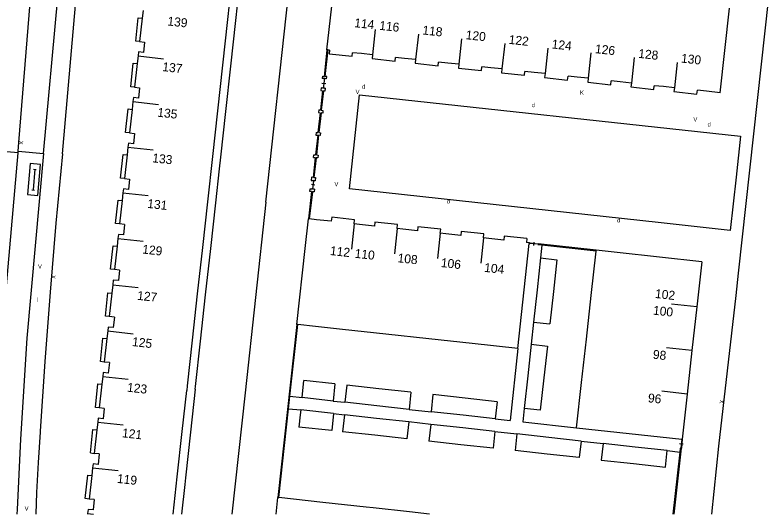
# Model space of a CAD drawing. Extents: x 134999 to 136502, y 457398 to 459002.
# Drawn here: x 136333.3 to 136421.3, y 457400 to 457458.7 of the extents above; entities that cross this region are included whole.
import ezdxf

# ---------------------------------------------------------------- set-up
doc = ezdxf.new("R2010")
doc.units = 0
for name, color, linetype in [('RI_DGTB_15', 7, 'Continuous'), ('RI_DGTB_2', 7, 'Continuous'), ('RI_DGTB_23', 7, 'Continuous'), ('RI_DGTB_29', 7, 'Continuous'), ('RI_DGTB_30', 7, 'Continuous'), ('RI_DGTB_35', 7, 'Continuous'), ('RI_DGTB_36', 7, 'Continuous'), ('RI_DGTB_43', 7, 'Continuous'), ('RI_DGTB_53', 7, 'Continuous'), ('RI_DGTB_6', 7, 'Continuous'), ('RI_DGTB_7', 7, 'Continuous')]:
    doc.layers.add(name, color=color, linetype=linetype)

msp = doc.modelspace()

# ---------------------------------------------------------------- linework, layer by layer
at = {"layer": 'RI_DGTB_15'}
for p, q in [((136375.693, 457457.011), (136375.37, 457454.029)), ((136380.759, 457456.46), (136380.436, 457453.478)), ((136385.836, 457455.908), (136385.513, 457452.926)), ((136390.911, 457455.355), (136390.588, 457452.373)), ((136395.98, 457454.804), (136395.657, 457451.822)), ((136347.786, 457453.897), (136350.769, 457453.574)), ((136401.048, 457454.252), (136400.725, 457451.27)), ((136406.126, 457453.699), (136405.803, 457450.717)), ((136411.188, 457453.149), (136410.865, 457450.167)), ((136347.196, 457448.531), (136350.179, 457448.208)), ((136346.604, 457443.163), (136349.587, 457442.84)), ((136346.013, 457437.796), (136348.996, 457437.473)), ((136373.2, 457434.152), (136372.877, 457431.17)), ((136378.274, 457433.598), (136377.951, 457430.616)), ((136345.422, 457432.428), (136348.405, 457432.105)), ((136383.334, 457433.046), (136383.011, 457430.064)), ((136388.421, 457432.489), (136388.098, 457429.507)), ((136344.823, 457426.986), (136347.806, 457426.663)), ((136413.492, 457424.368), (136410.51, 457424.692)), ((136344.224, 457421.544), (136347.207, 457421.221)), ((136412.918, 457419.244), (136409.936, 457419.568)), ((136343.634, 457416.176), (136346.617, 457415.853)), ((136412.368, 457414.117), (136409.386, 457414.441)), ((136343.043, 457410.808), (136346.026, 457410.485)), ((136342.451, 457405.441), (136345.434, 457405.118)), ((136341.86, 457400.073), (136342.538, 457400))]:
    msp.add_line(p, q, dxfattribs=at)
at = {"layer": 'RI_DGTB_2'}
for p, q in [((136369.997, 457454.628), (136371.381, 457467.081)), ((136416.252, 457449.58), (136417.345, 457459.531)), ((136347.52, 457455.642), (136347.823, 457458.405)), ((136347.823, 457458.405), (136348.277, 457458.355)), ((136347.973, 457455.592), (136347.52, 457455.642)), ((136374.068, 457454.171), (136372.999, 457454.287)), ((136375.37, 457454.029), (136374.068, 457454.171)), ((136379.141, 457453.619), (136378.072, 457453.736)), ((136380.436, 457453.478), (136379.141, 457453.619)), ((136346.928, 457450.28), (136347.233, 457453.043)), ((136347.233, 457453.043), (136347.687, 457452.993)), ((136384.207, 457453.068), (136383.138, 457453.185)), ((136385.513, 457452.926), (136384.207, 457453.068)), ((136389.284, 457452.515), (136388.215, 457452.632)), ((136390.588, 457452.373), (136389.284, 457452.515)), ((136394.358, 457451.963), (136393.289, 457452.079)), ((136395.657, 457451.822), (136394.358, 457451.963)), ((136399.427, 457451.411), (136398.358, 457451.527)), ((136400.725, 457451.27), (136399.427, 457451.411)), ((136404.495, 457450.86), (136403.426, 457450.976)), ((136405.803, 457450.717), (136404.495, 457450.86)), ((136409.573, 457450.307), (136408.502, 457450.397)), ((136410.865, 457450.167), (136409.573, 457450.307)), ((136414.636, 457449.756), (136413.567, 457449.872)), ((136416.252, 457449.58), (136414.636, 457449.756)), ((136346.309, 457444.9), (136346.64, 457447.66)), ((136346.79, 457444.847), (136346.309, 457444.9)), ((136345.746, 457439.537), (136346.05, 457442.3)), ((136346.05, 457442.3), (136346.504, 457442.25)), ((136346.2, 457439.487), (136345.746, 457439.537)), ((136345.155, 457434.18), (136345.459, 457436.942)), ((136345.459, 457436.942), (136345.914, 457436.892)), ((136345.61, 457434.129), (136345.155, 457434.18)), ((136346.206, 457434.063), (136345.61, 457434.129)), ((136367.451, 457431.244), (136367.827, 457434.739)), ((136373.254, 457434.621), (136370.57, 457434.914)), ((136378.318, 457434.068), (136375.634, 457434.361)), ((136383.39, 457433.514), (136380.705, 457433.807)), ((136383.334, 457433.046), (136383.39, 457433.514)), ((136388.46, 457432.96), (136385.776, 457433.254)), ((136346.071, 457432.84), (136345.475, 457432.907)), ((136388.421, 457432.489), (136388.46, 457432.96)), ((136393.53, 457432.407), (136390.845, 457432.7)), ((136393.53, 457432.407), (136393.479, 457431.939)), ((136344.564, 457428.811), (136344.869, 457431.574)), ((136344.869, 457431.574), (136345.323, 457431.524)), ((136393.81, 457431.903), (136393.479, 457431.939)), ((136366.477, 457422.312), (136367.451, 457431.244)), ((136404.135, 457430.777), (136401.661, 457431.047)), ((136414.089, 457429.69), (136404.135, 457430.777)), ((136345.019, 457428.761), (136344.564, 457428.811)), ((136345.615, 457428.695), (136345.019, 457428.761)), ((136345.48, 457427.473), (136344.884, 457427.538)), ((136343.95, 457423.279), (136344.253, 457426.042)), ((136344.253, 457426.042), (136344.714, 457425.991)), ((136345.006, 457423.162), (136344.41, 457423.228)), ((136343.363, 457417.931), (136343.666, 457420.694)), ((136343.666, 457420.694), (136344.125, 457420.644)), ((136343.821, 457417.881), (136343.363, 457417.931)), ((136344.417, 457417.815), (136343.821, 457417.881)), ((136344.283, 457416.593), (136343.687, 457416.658)), ((136342.775, 457412.551), (136343.078, 457415.314)), ((136343.078, 457415.314), (136343.533, 457415.264)), ((136343.229, 457412.501), (136342.775, 457412.551)), ((136343.825, 457412.435), (136343.229, 457412.501)), ((136343.69, 457411.212), (136343.095, 457411.278)), ((136342.184, 457407.184), (136342.488, 457409.947)), ((136342.488, 457409.947), (136342.942, 457409.897)), ((136342.184, 457407.184), (136342.638, 457407.134)), ((136343.234, 457407.068), (136342.638, 457407.134)), ((136343.099, 457405.845), (136342.503, 457405.911)), ((136341.592, 457401.815), (136341.897, 457404.578)), ((136341.897, 457404.578), (136342.351, 457404.528)), ((136353.289, 457403.463), (136352.889, 457400)), ((136342.643, 457401.699), (136342.047, 457401.765)), ((136364.023, 457400), (136364.238, 457401.954))]:
    msp.add_line(p, q, dxfattribs=at)
for points in [[(136358.892, 457463.632), (136358.296, 457458.189)], [(136359.278, 457458.082), (136359.875, 457463.525)], [(136348.377, 457459.266), (136348.277, 457458.355)], [(136348.277, 457458.355), (136347.973, 457455.592)], [(136358.296, 457458.189), (136357.708, 457452.821)], [(136358.69, 457452.714), (136359.278, 457458.082)], [(136347.973, 457455.592), (136348.569, 457455.526)], [(136348.569, 457455.526), (136348.434, 457454.303)], [(136347.838, 457454.369), (136347.786, 457453.897)], [(136348.434, 457454.303), (136347.838, 457454.369)], [(136370.093, 457454.617), (136369.997, 457454.628)], [(136370.299, 457454.592), (136370.093, 457454.617)], [(136370.299, 457454.592), (136370.253, 457454.157), (136372.953, 457453.863)], [(136347.786, 457453.897), (136347.687, 457452.993)], [(136372.953, 457453.863), (136372.999, 457454.287)], [(136375.37, 457454.029), (136375.325, 457453.6), (136378.025, 457453.306)], [(136378.025, 457453.306), (136378.072, 457453.736)], [(136347.687, 457452.993), (136347.383, 457450.23)], [(136357.708, 457452.821), (136357.12, 457447.454)], [(136358.102, 457447.347), (136358.69, 457452.714)], [(136380.436, 457453.478), (136380.39, 457453.04), (136383.09, 457452.746)], [(136383.09, 457452.746), (136383.138, 457453.185)], [(136385.513, 457452.926), (136385.466, 457452.481), (136388.166, 457452.187)], [(136388.166, 457452.187), (136388.215, 457452.632)], [(136390.588, 457452.373), (136390.541, 457451.931), (136393.241, 457451.637)], [(136393.241, 457451.637), (136393.289, 457452.079)], [(136395.657, 457451.822), (136395.608, 457451.36), (136398.308, 457451.066)], [(136398.308, 457451.066), (136398.358, 457451.527)], [(136400.725, 457451.27), (136400.676, 457450.808), (136403.376, 457450.514)], [(136403.376, 457450.514), (136403.426, 457450.976)], [(136347.383, 457450.23), (136346.928, 457450.28)], [(136347.383, 457450.23), (136347.979, 457450.164)], [(136347.979, 457450.164), (136347.844, 457448.942)], [(136405.803, 457450.717), (136405.755, 457450.261), (136408.455, 457449.967)], [(136408.455, 457449.967), (136408.502, 457450.397)], [(136410.865, 457450.167), (136410.817, 457449.708), (136413.517, 457449.414)], [(136413.517, 457449.414), (136413.567, 457449.872)], [(136347.196, 457448.531), (136347.094, 457447.61)], [(136347.248, 457449.007), (136347.196, 457448.531)], [(136347.844, 457448.942), (136347.248, 457449.007)], [(136346.64, 457447.66), (136347.094, 457447.61)], [(136347.094, 457447.61), (136346.79, 457444.847)], [(136357.12, 457447.454), (136356.532, 457442.085)], [(136357.514, 457441.978), (136358.102, 457447.347)], [(136346.79, 457444.847), (136347.386, 457444.781)], [(136347.386, 457444.781), (136347.251, 457443.558)], [(136346.604, 457443.163), (136346.504, 457442.25)], [(136346.655, 457443.624), (136346.604, 457443.163)], [(136347.251, 457443.558), (136346.655, 457443.624)], [(136346.504, 457442.25), (136346.2, 457439.487)], [(136356.532, 457442.085), (136355.944, 457436.717)], [(136357.367, 457440.638), (136357.514, 457441.978)], [(136356.924, 457436.611), (136357.367, 457440.638)], [(136346.2, 457439.487), (136346.796, 457439.421)], [(136346.796, 457439.421), (136346.661, 457438.198)], [(136346.013, 457437.796), (136345.914, 457436.892)], [(136346.065, 457438.264), (136346.013, 457437.796)], [(136346.661, 457438.198), (136346.065, 457438.264)], [(136345.914, 457436.892), (136345.61, 457434.129)], [(136355.944, 457436.717), (136355.356, 457431.349)], [(136356.334, 457431.243), (136356.924, 457436.611)], [(136367.831, 457434.739), (136367.827, 457434.739)], [(136367.93, 457434.728), (136367.831, 457434.739)], [(136368.776, 457434.635), (136367.93, 457434.728)], [(136370.516, 457434.445), (136368.776, 457434.635)], [(136370.57, 457434.914), (136370.516, 457434.445)], [(136373.2, 457434.152), (136373.254, 457434.621)], [(136373.843, 457434.082), (136373.2, 457434.152)], [(136375.634, 457434.361), (136375.583, 457433.892)], [(136346.206, 457434.063), (136346.071, 457432.84)], [(136375.583, 457433.892), (136373.843, 457434.082)], [(136378.274, 457433.598), (136378.318, 457434.068)], [(136378.927, 457433.527), (136378.274, 457433.598)], [(136380.667, 457433.337), (136378.927, 457433.527)], [(136380.705, 457433.807), (136380.667, 457433.337)], [(136385.776, 457433.254), (136385.737, 457432.784)], [(136345.422, 457432.428), (136345.323, 457431.524)], [(136345.475, 457432.907), (136345.422, 457432.428)], [(136383.997, 457432.974), (136383.334, 457433.046)], [(136385.737, 457432.784), (136383.997, 457432.974)], [(136389.054, 457432.42), (136388.421, 457432.489)], [(136390.794, 457432.231), (136389.054, 457432.42)], [(136390.845, 457432.7), (136390.794, 457432.231)], [(136345.323, 457431.524), (136345.019, 457428.761)], [(136392.461, 457419.469), (136393.804, 457431.852)], [(136393.804, 457431.852), (136393.81, 457431.903)], [(136355.356, 457431.349), (136354.76, 457425.906)], [(136355.736, 457425.8), (136356.334, 457431.243)], [(136401.076, 457425.716), (136401.65, 457430.948)], [(136401.65, 457430.948), (136401.661, 457431.047)], [(136414.089, 457429.69), (136413.492, 457424.368)], [(136345.615, 457428.695), (136345.48, 457427.473)], [(136344.884, 457427.538), (136344.823, 457426.986)], [(136344.823, 457426.986), (136344.714, 457425.991)], [(136344.714, 457425.991), (136344.41, 457423.228)], [(136354.76, 457425.906), (136354.164, 457420.464)], [(136355.138, 457420.358), (136355.736, 457425.8)], [(136400.513, 457420.59), (136401.076, 457425.716)], [(136413.492, 457424.368), (136412.918, 457419.244)], [(136344.41, 457423.228), (136343.95, 457423.279)], [(136345.006, 457423.162), (136344.871, 457421.939)], [(136344.275, 457422.005), (136344.224, 457421.544)], [(136344.871, 457421.939), (136344.275, 457422.005)], [(136366.595, 457422.299), (136366.477, 457422.312)], [(136368.643, 457422.074), (136366.595, 457422.299)], [(136371.851, 457421.723), (136368.643, 457422.074)], [(136344.224, 457421.544), (136344.125, 457420.644)], [(136376.925, 457421.168), (136371.851, 457421.723)], [(136381.985, 457420.615), (136376.925, 457421.168)], [(136344.125, 457420.644), (136343.821, 457417.881)], [(136354.164, 457420.464), (136353.575, 457415.097)], [(136354.548, 457414.991), (136355.138, 457420.358)], [(136387.072, 457420.059), (136381.985, 457420.615)], [(136392.461, 457419.469), (136387.072, 457420.059)], [(136399.951, 457415.465), (136400.513, 457420.59)], [(136412.918, 457419.244), (136412.368, 457414.117)], [(136344.417, 457417.815), (136344.283, 457416.593)], [(136343.687, 457416.658), (136343.634, 457416.176)], [(136343.634, 457416.176), (136343.533, 457415.264)], [(136343.533, 457415.264), (136343.229, 457412.501)], [(136353.575, 457415.097), (136353.514, 457414.536)], [(136354.517, 457414.709), (136354.548, 457414.991)], [(136399.368, 457410.154), (136399.951, 457415.465)], [(136352.982, 457409.729), (136353.514, 457414.536)], [(136354.517, 457414.709), (136353.961, 457409.623)], [(136412.368, 457414.117), (136411.796, 457408.793)], [(136343.825, 457412.435), (136343.69, 457411.212)], [(136343.095, 457411.278), (136343.043, 457410.808)], [(136343.043, 457410.808), (136342.942, 457409.897)], [(136342.942, 457409.897), (136342.638, 457407.134)], [(136352.387, 457404.362), (136352.982, 457409.729)], [(136353.961, 457409.623), (136353.375, 457404.255)], [(136399.368, 457410.154), (136411.747, 457408.798)], [(136411.747, 457408.798), (136411.796, 457408.793)], [(136343.234, 457407.068), (136343.099, 457405.845)], [(136342.451, 457405.441), (136342.351, 457404.528)], [(136342.503, 457405.911), (136342.451, 457405.441)], [(136342.351, 457404.528), (136342.047, 457401.765)], [(136351.904, 457400), (136352.387, 457404.362)], [(136353.375, 457404.255), (136353.289, 457403.463)], [(136342.047, 457401.765), (136341.592, 457401.815)], [(136342.643, 457401.699), (136342.508, 457400.477)], [(136364.238, 457401.954), (136364.341, 457401.943)], [(136369.519, 457401.375), (136364.341, 457401.943)], [(136374.615, 457400.815), (136369.519, 457401.375)], [(136379.709, 457400.257), (136375.426, 457400.726), (136374.615, 457400.815)], [(136341.86, 457400.073), (136341.852, 457400)], [(136341.912, 457400.542), (136341.86, 457400.073)], [(136342.508, 457400.477), (136341.912, 457400.542)], [(136382.055, 457400), (136379.709, 457400.257)]]:
    msp.add_lwpolyline(points, dxfattribs=at)
at = {"layer": 'RI_DGTB_23'}
for p, q in [((136393.81, 457431.903), (136394.864, 457431.788)), ((136411.796, 457408.793), (136411.681, 457407.739))]:
    msp.add_line(p, q, dxfattribs=at)
at = {"layer": 'RI_DGTB_29'}
for points in [[(136334.793, 457437.586), (136335.988, 457437.478), (136336.316, 457441.127), (136335.121, 457441.234), (136334.793, 457437.586)], [(136335.664, 457440.572), (136335.445, 457438.14)], [(136335.515, 457440.585), (136335.813, 457440.558)], [(136335.296, 457438.153), (136335.595, 457438.126)]]:
    msp.add_lwpolyline(points, dxfattribs=at)
at = {"layer": 'RI_DGTB_53'}
for p, q in [((136418.405, 457428.328), (136424.169, 457481.084)), ((136336.683, 457442.434), (136338.801, 457465.882)), ((136338.913, 457442.388), (136340.885, 457465.016)), ((136333.787, 457443.702), (136335.089, 457460.148)), ((136369.474, 457451.516), (136369.448, 457451.262)), ((136369.474, 457451.516), (136369.673, 457451.496)), ((136369.702, 457451.234), (136369.579, 457450.123)), ((136369.591, 457451.246), (136369.813, 457451.222)), ((136369.979, 457451.465), (136369.772, 457451.486)), ((136369.952, 457451.206), (136369.979, 457451.465)), ((136369.323, 457450.153), (136369.287, 457449.825)), ((136369.418, 457450.703), (136369.863, 457450.654)), ((136369.468, 457450.135), (136369.69, 457450.111)), ((136369.811, 457450.099), (136369.775, 457449.771)), ((136369.486, 457449.803), (136369.236, 457447.543)), ((136369.287, 457449.825), (136369.486, 457449.803)), ((136369.585, 457449.792), (136369.335, 457447.532)), ((136369.775, 457449.771), (136369.585, 457449.792)), ((136372.639, 457438.259), (136373.848, 457449.34)), ((136373.848, 457449.34), (136418.637, 457444.451)), ((136369.053, 457447.563), (136369.015, 457447.232)), ((136369.053, 457447.563), (136369.236, 457447.543)), ((136369.335, 457447.532), (136369.541, 457447.496)), ((136369.541, 457447.496), (136369.506, 457447.176)), ((136369.214, 457447.209), (136368.951, 457444.889)), ((136369.015, 457447.232), (136369.214, 457447.209)), ((136369.313, 457447.198), (136369.05, 457444.878)), ((136369.506, 457447.176), (136369.313, 457447.198)), ((136368.749, 457444.912), (136368.716, 457444.597)), ((136368.749, 457444.912), (136368.951, 457444.889)), ((136369.05, 457444.878), (136369.251, 457444.849)), ((136369.251, 457444.849), (136369.216, 457444.536)), ((136368.915, 457444.576), (136368.669, 457442.258)), ((136368.716, 457444.597), (136368.915, 457444.576)), ((136369.014, 457444.565), (136368.768, 457442.247)), ((136369.216, 457444.536), (136369.014, 457444.565)), ((136418.637, 457444.451), (136418.113, 457439.652)), ((136368.436, 457441.961), (136368.47, 457442.279)), ((136368.47, 457442.279), (136368.669, 457442.258)), ((136368.768, 457442.247), (136368.962, 457442.22)), ((136368.962, 457442.22), (136368.928, 457441.901)), ((136368.625, 457441.941), (136368.377, 457439.618)), ((136368.436, 457441.961), (136368.625, 457441.941)), ((136368.724, 457441.93), (136368.476, 457439.608)), ((136368.928, 457441.901), (136368.724, 457441.93)), ((136368.177, 457439.639), (136368.137, 457439.258)), ((136368.377, 457439.618), (136368.177, 457439.639)), ((136368.476, 457439.608), (136368.675, 457439.583)), ((136368.675, 457439.583), (136368.634, 457439.205)), ((136418.113, 457439.652), (136417.427, 457433.367)), ((136368.137, 457439.258), (136368.336, 457439.237)), ((136368.597, 457438.707), (136368.205, 457438.759)), ((136368.465, 457439.223), (136368.336, 457439.237)), ((136368.336, 457438.243), (136368.465, 457439.224)), ((136368.336, 457438.238), (136368.465, 457439.223)), ((136368.563, 457439.211), (136368.367, 457439.237)), ((136368.634, 457439.205), (136368.465, 457439.223)), ((136367.995, 457437.96), (136368.031, 457438.273)), ((136368.194, 457437.937), (136367.995, 457437.96)), ((136368.031, 457438.273), (136368.23, 457438.25)), ((136368.435, 457438.23), (136368.238, 457438.256)), ((136368.53, 457438.215), (136368.494, 457437.902)), ((136408.967, 457434.291), (136372.639, 457438.259)), ((136417.427, 457433.367), (136408.967, 457434.291)), ((136393.815, 457431.957), (136393.793, 457431.747)), ((136394.858, 457431.738), (136393.804, 457431.852)), ((136394.354, 457432.006), (136394.308, 457431.584)), ((136394.869, 457431.843), (136394.847, 457431.633)), ((136401.661, 457431.047), (136394.864, 457431.788)), ((136366.477, 457422.312), (136364.238, 457401.954)), ((136394.311, 457422.58), (136394.029, 457419.979)), ((136392.461, 457419.469), (136391.544, 457411.015)), ((136370.72, 457413.298), (136372.105, 457413.158)), ((136379.659, 457412.32), (136382.251, 457412.045)), ((136393.209, 457412.424), (136393.038, 457410.85)), ((136370.78, 457411.817), (136372.072, 457411.673)), ((136382.205, 457410.549), (136379.625, 457410.835)), ((136389.805, 457411.206), (136391.544, 457411.015)), ((136393.038, 457410.85), (136399.368, 457410.154)), ((136389.759, 457409.71), (136392.339, 457409.423)), ((136411.747, 457408.798), (136411.632, 457407.744)), ((136411.642, 457408.81), (136411.852, 457408.786)), ((136399.892, 457408.585), (136402.483, 457408.298)), ((136410.835, 457400), (136411.681, 457407.739)), ((136411.479, 457408.294), (136411.9, 457408.248)), ((136411.527, 457407.755), (136411.737, 457407.732)), ((136415.276, 457400), (136416.1, 457407.99)), ((136333.57, 457400.538), (136333.549, 457400))]:
    msp.add_line(p, q, dxfattribs=at)
for points in [[(136369.997, 457454.628), (136369.673, 457451.496)], [(136370.093, 457454.617), (136369.772, 457451.486)], [(136369.702, 457451.234), (136369.448, 457451.262)], [(136369.702, 457451.234), (136369.579, 457450.125)], [(136369.952, 457451.206), (136369.702, 457451.234)], [(136369.579, 457450.125), (136369.323, 457450.153)], [(136369.811, 457450.099), (136369.579, 457450.125)], [(136333.698, 457442.681), (136333.787, 457443.702)], [(136333.682, 457442.502), (136330.547, 457442.792), (136328.449, 457419.934), (136328.168, 457408.395), (136328.311, 457408.352)], [(136328.417, 457408.855), (136331.69, 457420.12), (136331.919, 457422.378), (136333.682, 457442.502)], [(136336.683, 457442.434), (136334.709, 457420.68), (136333.973, 457408.795), (136333.57, 457400.538)], [(136333.682, 457442.502), (136333.698, 457442.681)], [(136333.698, 457442.681), (136336.683, 457442.434)], [(136338.913, 457442.388), (136338.138, 457434.243), (136337.442, 457426.09), (136336.825, 457417.931), (136336.289, 457409.766), (136336.28, 457409.624)], [(136368.194, 457437.937), (136367.831, 457434.739)], [(136368.494, 457437.902), (136368.294, 457437.925), (136367.93, 457434.728)], [(136368.336, 457438.238), (136368.23, 457438.25)], [(136368.53, 457438.215), (136368.336, 457438.238)], [(136394.858, 457431.738), (136393.804, 457431.852)], [(136394.858, 457431.738), (136394.853, 457431.689)], [(136395.294, 457431.641), (136394.853, 457431.689)], [(136394.864, 457431.788), (136394.858, 457431.738)], [(136395.294, 457431.641), (136395.131, 457430.136)], [(136401.65, 457430.948), (136395.294, 457431.641)], [(136416.1, 457407.99), (136418.12, 457425.72), (136418.405, 457428.328)], [(136365.66, 457413.852), (136366.595, 457422.299)], [(136365.499, 457412.397), (136365.66, 457413.852)], [(136365.66, 457413.852), (136367.087, 457413.701)], [(136364.341, 457401.943), (136365.499, 457412.397)], [(136365.499, 457412.397), (136366.933, 457412.245)], [(136336.28, 457409.624), (136336.026, 457406.074), (136335.851, 457402.519), (136335.779, 457400)], [(136411.747, 457408.798), (136411.632, 457407.744)], [(136411.532, 457407.295), (136411.582, 457407.75)], [(136411.582, 457407.75), (136411.632, 457407.744)], [(136411.632, 457407.744), (136411.681, 457407.739)], [(136410.031, 457407.46), (136411.532, 457407.295)], [(136410.735, 457400), (136411.532, 457407.295)]]:
    msp.add_lwpolyline(points, dxfattribs=at)
at = {"layer": 'RI_DGTB_6'}
for p, q in [((136394.311, 457422.58), (136396.233, 457422.371)), ((136370.943, 457415.306), (136367.306, 457415.71)), ((136370.943, 457415.306), (136370.72, 457413.298)), ((136372.328, 457415.166), (136372.105, 457413.158)), ((136379.882, 457414.328), (136379.659, 457412.32)), ((136382.474, 457414.053), (136382.251, 457412.045)), ((136370.72, 457413.298), (136367.087, 457413.701)), ((136390.028, 457413.214), (136389.805, 457411.206)), ((136366.933, 457412.245), (136366.87, 457411.66)), ((136370.78, 457411.817), (136366.933, 457412.245)), ((136395.098, 457412.218), (136393.209, 457412.424)), ((136366.87, 457411.66), (136366.715, 457410.24)), ((136370.78, 457411.817), (136370.562, 457409.82)), ((136372.072, 457411.673), (136371.853, 457409.679)), ((136379.625, 457410.835), (136379.409, 457408.855)), ((136382.205, 457410.549), (136381.989, 457408.573)), ((136370.562, 457409.82), (136366.715, 457410.24)), ((136389.759, 457409.71), (136389.544, 457407.749)), ((136392.339, 457409.423), (136392.125, 457407.467)), ((136399.892, 457408.585), (136399.68, 457406.642)), ((136402.483, 457408.298), (136402.272, 457406.359)), ((136406.247, 457407.88), (136402.483, 457408.298)), ((136410.031, 457407.46), (136406.247, 457407.88)), ((136409.821, 457405.535), (136410.031, 457407.46))]:
    msp.add_line(p, q, dxfattribs=at)
for points in [[(136395.131, 457430.136), (136394.725, 457426.39)], [(136395.131, 457430.136), (136397.054, 457429.922), (136396.636, 457426.182)], [(136394.725, 457426.39), (136394.311, 457422.58)], [(136396.636, 457426.182), (136396.233, 457422.371)], [(136394.029, 457419.979), (136393.624, 457416.249)], [(136394.029, 457419.979), (136395.93, 457419.772), (136395.519, 457416.043)], [(136367.087, 457413.701), (136367.306, 457415.71)], [(136393.624, 457416.249), (136393.209, 457412.424)], [(136395.519, 457416.043), (136395.098, 457412.218)], [(136376.105, 457414.747), (136372.328, 457415.166)], [(136379.882, 457414.328), (136376.105, 457414.747)], [(136386.251, 457413.634), (136382.474, 457414.053)], [(136375.882, 457412.739), (136372.105, 457413.158)], [(136390.028, 457413.214), (136386.251, 457413.634)], [(136379.659, 457412.32), (136375.882, 457412.739)], [(136375.848, 457411.254), (136372.072, 457411.673)], [(136386.028, 457411.626), (136382.251, 457412.045)], [(136389.805, 457411.206), (136386.028, 457411.626)], [(136379.625, 457410.835), (136375.848, 457411.254)], [(136385.982, 457410.13), (136382.205, 457410.549)], [(136375.631, 457409.267), (136371.853, 457409.679)], [(136389.759, 457409.71), (136385.982, 457410.13)], [(136379.409, 457408.855), (136375.631, 457409.267)], [(136396.116, 457409.004), (136392.339, 457409.423)], [(136399.892, 457408.585), (136396.116, 457409.004)], [(136385.767, 457408.161), (136381.989, 457408.573)], [(136389.544, 457407.749), (136385.767, 457408.161)], [(136395.903, 457407.054), (136392.125, 457407.467)], [(136399.68, 457406.642), (136395.903, 457407.054)], [(136402.272, 457406.359), (136406.036, 457405.948)], [(136406.036, 457405.948), (136409.821, 457405.535)]]:
    msp.add_lwpolyline(points, dxfattribs=at)
at = {"layer": 'RI_DGTB_7'}
for p, q in [((136362.824, 457436.68), (136369.757, 457500.344)), ((136362.824, 457436.68), (136360.381, 457414.245)), ((136360.381, 457414.245), (136358.81, 457400))]:
    msp.add_line(p, q, dxfattribs=at)

# ---------------------------------------------------------------- texts
at = {"layer": 'RI_DGTB_29'}
for p in [(136374.13, 457450.038), (136394.109, 457447.875), (136414.767, 457445.602), (136384.101, 457436.547), (136404.122, 457434.323)]:
    msp.add_text('d', height=0.5, dxfattribs=at).set_placement(p)
at = {"layer": 'RI_DGTB_30'}
for s, p in [('V', (136373.372, 457449.417)), ('K', (136399.763, 457449.336)), ('V', (136413.097, 457446.181)), ('V', (136370.883, 457438.572)), ('V', (136336.024, 457428.884)), ('V', (136334.455, 457400.404))]:
    msp.add_text(s, height=0.5, dxfattribs=at).set_placement(p)
for rotation, p in [(264.99345, (136333.809, 457443.951)), (264.77861, (136337.613, 457428.151)), (83.49337, (136416.662, 457412.958))]:
    msp.add_text('X', height=0.5, rotation=rotation, dxfattribs=at).set_placement(p)
at = {"layer": 'RI_DGTB_35'}
for s, p in [('114', (136373.182, 457457.296)), ('130', (136411.609, 457453.127)), ('112', (136370.326, 457430.486)), ('104', (136388.458, 457428.504)), ('102', (136408.546, 457425.432)), ('96', (136407.712, 457413.161))]:
    msp.add_text(s, height=1.054, rotation=353.8033, dxfattribs=at).set_placement(p)
at = {"layer": 'RI_DGTB_36'}
for s, rotation, p in [('139', 353.8023, (136351.203, 457457.498)), ('116', 353.8033, (136376.119, 457456.988)), ('118', 353.8033, (136381.192, 457456.44)), ('120', 353.8033, (136386.284, 457455.877)), ('122', 353.8033, (136391.339, 457455.333)), ('124', 353.8033, (136396.398, 457454.794)), ('126', 353.8033, (136401.492, 457454.239)), ('128', 353.8033, (136406.578, 457453.689)), ('137', 353.8023, (136350.612, 457452.129)), ('135', 353.8023, (136350.022, 457446.763)), ('133', 353.8023, (136349.43, 457441.395)), ('131', 353.8023, (136348.839, 457436.028)), ('129', 353.8023, (136348.248, 457430.66)), ('110', 353.8033, (136373.227, 457430.164)), ('108', 353.8033, (136378.273, 457429.631)), ('106', 353.8033, (136383.364, 457429.073)), ('127', 353.8023, (136347.649, 457425.218)), ('100', 353.8033, (136408.31, 457423.469)), ('125', 353.8023, (136347.05, 457419.776)), ('98', 353.8033, (136408.293, 457418.284)), ('123', 353.8023, (136346.46, 457414.408)), ('121', 353.8023, (136345.869, 457409.04)), ('119', 353.8023, (136345.277, 457403.673))]:
    msp.add_text(s, height=1.054, rotation=rotation, dxfattribs=at).set_placement(p)
at = {"layer": 'RI_DGTB_43'}
msp.add_text('l', height=0.5, dxfattribs=at).set_placement((136335.891, 457424.96))

doc.saveas('drawing.dxf')
